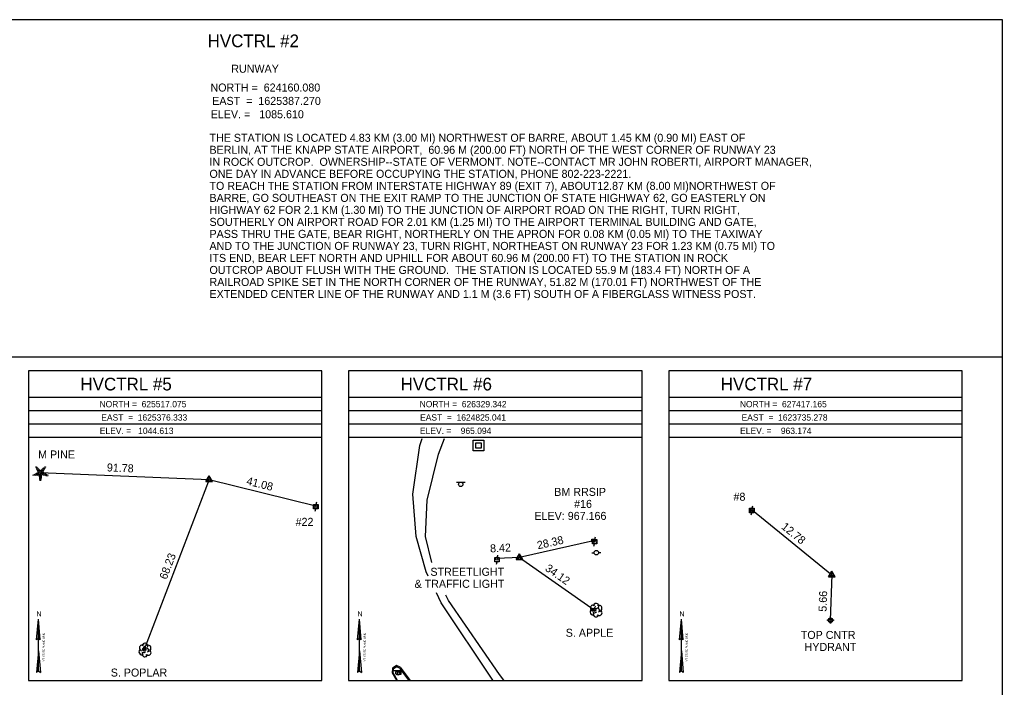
# Model space of a CAD drawing. Extents: x 1624370 to 1625010, y 624015 to 624435.
# Drawn here: x 1624641.5 to 1625009.8, y 624185.4 to 624435.5 of the extents above; entities that cross this region are included whole.
import ezdxf

# ---------------------------------------------------------------- set-up
doc = ezdxf.new("R2010")
doc.units = 0
for name, color, linetype in [('C_C', 7, 'Continuous'), ('CBP', 7, 'Continuous'), ('CPBM', 7, 'Continuous'), ('CPSM', 7, 'Continuous'), ('Default', 7, 'Continuous'), ('DS', 7, 'Continuous'), ('L_C', 7, 'Continuous'), ('LTC', 7, 'Continuous'), ('LTD', 7, 'Continuous'), ('NBL1', 7, 'Continuous'), ('NBL2', 7, 'Continuous'), ('NNA_P', 7, 'Continuous'), ('PET', 7, 'Continuous'), ('PSP', 7, 'Continuous'), ('RC', 7, 'Continuous'), ('SRM', 7, 'Continuous'), ('SSGN', 7, 'Continuous'), ('U_C', 7, 'Continuous'), ('ULP', 7, 'Continuous'), ('UP', 7, 'Continuous'), ('UWFH', 7, 'Continuous')]:
    doc.layers.add(name, color=color, linetype=linetype)

msp = doc.modelspace()

# ---------------------------------------------------------------- linework, layer by layer
at = {"layer": 'CBP'}
for centre, radius in [((1624649.13, 624265.8), 0.625), ((1624649.13, 624265.8), 0.0833), ((1624752.44, 624253.33), 0.625), ((1624752.44, 624253.33), 0.0833), ((1624916.17, 624251.76), 0.625), ((1624916.17, 624251.76), 0.0833), ((1624856.56, 624240.21), 0.625), ((1624856.56, 624240.21), 0.0833), ((1624820.45, 624233.6), 0.625), ((1624820.45, 624233.6), 0.0833), ((1624856.84, 624214.46), 0.625), ((1624856.84, 624214.46), 0.0833), ((1624945.27, 624210.52), 0.625), ((1624945.27, 624210.52), 0.0833), ((1624688.15, 624199.5), 0.625), ((1624688.15, 624199.5), 0.0833)]:
    msp.add_circle(centre, radius, dxfattribs=at)
at = {"layer": 'CPBM'}
for p, q in [((1624855.95, 624239.93), (1624855.95, 624240.93)), ((1624855.95, 624240.93), (1624856.95, 624240.93)), ((1624856.95, 624239.93), (1624855.95, 624239.93)), ((1624856.45, 624240.43), (1624856.45, 624240.43)), ((1624856.45, 624240.43), (1624856.45, 624240.43)), ((1624856.95, 624240.93), (1624856.95, 624239.93))]:
    msp.add_line(p, q, dxfattribs=at)
at = {"layer": 'CPSM'}
for p, q in [((1624711.31, 624262.5), (1624712.56, 624264.67)), ((1624711.31, 624262.5), (1624712.56, 624263.22)), ((1624711.31, 624262.5), (1624713.81, 624262.5)), ((1624713.81, 624262.5), (1624712.56, 624264.67)), ((1624712.56, 624263.22), (1624712.56, 624264.67)), ((1624712.56, 624263.22), (1624712.56, 624263.22)), ((1624712.56, 624263.22), (1624713.81, 624262.5)), ((1624827.61, 624233.28), (1624828.86, 624235.45)), ((1624827.61, 624233.28), (1624828.86, 624234)), ((1624827.61, 624233.28), (1624830.11, 624233.28)), ((1624830.11, 624233.28), (1624828.86, 624235.45)), ((1624828.86, 624234), (1624828.86, 624235.45)), ((1624828.86, 624234), (1624828.86, 624234)), ((1624828.86, 624234), (1624830.11, 624233.28)), ((1624944.61, 624226.78), (1624945.86, 624228.95)), ((1624947.11, 624226.78), (1624945.86, 624228.95)), ((1624945.86, 624227.51), (1624945.86, 624228.95)), ((1624944.61, 624226.78), (1624945.86, 624227.51)), ((1624944.61, 624226.78), (1624947.11, 624226.78)), ((1624945.86, 624227.51), (1624945.86, 624227.51)), ((1624945.86, 624227.51), (1624947.11, 624226.78))]:
    msp.add_line(p, q, dxfattribs=at)
at = {"layer": 'Default'}
for p, q in [((1624649.13, 624265.8), (1624712.56, 624263.22)), ((1624712.56, 624263.22), (1624688.15, 624199.5)), ((1624712.56, 624263.22), (1624752.44, 624253.33)), ((1624916.17, 624251.76), (1624945.87, 624227.5)), ((1624856.56, 624240.21), (1624828.86, 624234)), ((1624828.86, 624234), (1624820.45, 624233.6)), ((1624828.86, 624234), (1624856.84, 624214.46)), ((1624945.87, 624227.5), (1624945.27, 624210.52))]:
    msp.add_line(p, q, dxfattribs=at)
at = {"layer": 'DS'}
for p, q in [((1624811.47, 624277.96), (1624815.47, 624277.96)), ((1624811.47, 624273.96), (1624811.47, 624277.96)), ((1624812.47, 624274.96), (1624812.47, 624276.96)), ((1624812.47, 624276.96), (1624814.47, 624276.96)), ((1624814.47, 624276.96), (1624814.47, 624274.96)), ((1624815.47, 624277.96), (1624815.47, 624273.96)), ((1624815.47, 624273.96), (1624811.47, 624273.96)), ((1624814.47, 624274.96), (1624812.47, 624274.96)), ((1624813.48, 624275.96), (1624813.48, 624275.96)), ((1624813.48, 624275.96), (1624813.48, 624275.96))]:
    msp.add_line(p, q, dxfattribs=at)
at = {"layer": 'LTC'}
for p, q in [((1624646.9, 624265.37), (1624647.11, 624264.72)), ((1624647.36, 624265.59), (1624647.63, 624264.75)), ((1624647.42, 624267.88), (1624647.77, 624268.14)), ((1624647.62, 624267.41), (1624648.15, 624267.8)), ((1624647.81, 624265.81), (1624648.14, 624264.79)), ((1624647.83, 624266.95), (1624648.54, 624267.46)), ((1624648.04, 624266.48), (1624648.92, 624267.12)), ((1624648.27, 624266.03), (1624649.28, 624266.76)), ((1624648.27, 624266.03), (1624648.66, 624264.83)), ((1624649.28, 624266.76), (1624650.28, 624266.04)), ((1624649.7, 624267.07), (1624650.51, 624266.48)), ((1624650.28, 624266.04), (1624649.89, 624264.83)), ((1624650.07, 624267.42), (1624650.75, 624266.93)), ((1624650.71, 624265.76), (1624650.38, 624264.72)), ((1624650.44, 624267.77), (1624650.99, 624267.37)), ((1624650.81, 624268.12), (1624651.23, 624267.81)), ((1624651.16, 624265.51), (1624650.87, 624264.63)), ((1624651.6, 624265.26), (1624651.37, 624264.53)), ((1624646.45, 624265.16), (1624646.6, 624264.69)), ((1624649.89, 624264.83), (1624648.66, 624264.83)), ((1624649.85, 624264.33), (1624648.7, 624264.33)), ((1624649.76, 624263.83), (1624648.78, 624263.83)), ((1624649.68, 624263.33), (1624648.85, 624263.33)), ((1624649.6, 624262.83), (1624648.92, 624262.83)), ((1624652.05, 624265.01), (1624651.86, 624264.44))]:
    msp.add_line(p, q, dxfattribs=at)
at = {"layer": 'LTD'}
for p, q in [((1624857.47, 624214.33), (1624857.47, 624214.33)), ((1624857.47, 624214.33), (1624857.47, 624214.33)), ((1624688.44, 624199.42), (1624688.44, 624199.42)), ((1624688.44, 624199.42), (1624688.44, 624199.42))]:
    msp.add_line(p, q, dxfattribs=at)
for centre in [(1624857.52, 624215.76), (1624688.48, 624200.86)]:
    msp.add_arc(centre, 1.05, 335.5272, 180.9563, dxfattribs=at)
for centre, major_axis, ratio, start_param, end_param in [((1624856.39, 624213.62), (0.58, -1.04), 0.959034, 3.141593, 6.283185), ((1624856.68, 624215), (1.21, -0.51), 0.895232, 1.570796, 4.712389), ((1624857.01, 624213.58), (-0.625, -0.083), 0.423636, 0, 3.141593), ((1624857.26, 624214.79), (-0.208, -0.792), 0.645439, 3.141593, 6.283185), ((1624857.97, 624214.16), (-0.5, 0.667), 0.989748, 3.141593, 6.283185), ((1624858.47, 624213.5), (-1.09, 0.79), 0.841452, 1.570796, 4.712389), ((1624858.51, 624214.91), (-1.14, -0.48), 0.949671, 1.570796, 4.712389), ((1624857.47, 624212.83), (0.26, 1.06), 0.942809, 1.570796, 4.712389), ((1624687.35, 624198.72), (0.58, -1.04), 0.959034, 3.141593, 6.283185), ((1624687.65, 624200.09), (1.21, -0.51), 0.895232, 1.570796, 4.712389), ((1624688.23, 624199.88), (-0.208, -0.792), 0.645439, 3.141593, 6.283185), ((1624688.94, 624199.26), (-0.5, 0.667), 0.989748, 3.141593, 6.283185), ((1624689.44, 624198.59), (-1.09, 0.79), 0.841452, 1.570796, 4.712389), ((1624689.48, 624200.01), (-1.14, -0.48), 0.949671, 1.570796, 4.712389), ((1624688.44, 624197.92), (0.26, 1.06), 0.942809, 1.570796, 4.712389), ((1624687.98, 624198.67), (-0.625, -0.083), 0.423636, 0, 3.141593)]:
    msp.add_ellipse(centre, major_axis=major_axis, ratio=ratio, start_param=start_param, end_param=end_param, dxfattribs=at)
at = {"layer": 'NBL1'}
msp.add_lwpolyline([(1624369.79, 624015.47), (1625009.79, 624015.47), (1625009.79, 624435.47), (1624369.79, 624435.47)], close=True, dxfattribs=at)
at = {"layer": 'NBL2'}
for p, q in [((1624369.79, 624309.14), (1625009.79, 624309.14)), ((1624754.79, 624293.97), (1624644.79, 624293.97)), ((1624874.79, 624293.97), (1624764.79, 624293.97)), ((1624994.79, 624293.97), (1624884.79, 624293.97)), ((1624754.79, 624288.97), (1624644.79, 624288.97)), ((1624874.79, 624288.97), (1624764.79, 624288.97)), ((1624994.79, 624288.97), (1624884.79, 624288.97)), ((1624754.79, 624283.97), (1624644.79, 624283.97)), ((1624874.79, 624283.97), (1624764.79, 624283.97)), ((1624994.79, 624283.97), (1624884.79, 624283.97)), ((1624754.79, 624278.97), (1624644.79, 624278.97)), ((1624874.79, 624278.97), (1624764.79, 624278.97)), ((1624994.79, 624278.97), (1624884.79, 624278.97))]:
    msp.add_line(p, q, dxfattribs=at)
for points in [[(1624644.79, 624187.97), (1624754.79, 624187.97), (1624754.79, 624303.97), (1624644.79, 624303.97)], [(1624764.79, 624187.97), (1624874.79, 624187.97), (1624874.79, 624303.97), (1624764.79, 624303.97)], [(1624884.79, 624187.97), (1624994.79, 624187.97), (1624994.79, 624303.97), (1624884.79, 624303.97)]]:
    msp.add_lwpolyline(points, close=True, dxfattribs=at)
at = {"layer": 'NNA_P'}
for p, q in [((1624647.81, 624203.13), (1624648.51, 624210.92)), ((1624648.51, 624191.55), (1624648.51, 624210.92)), ((1624649.2, 624203.13), (1624648.51, 624210.92)), ((1624768.13, 624203.13), (1624768.82, 624210.92)), ((1624768.82, 624191.55), (1624768.82, 624210.92)), ((1624769.51, 624203.13), (1624768.82, 624210.92)), ((1624888.79, 624203.13), (1624889.49, 624210.92)), ((1624889.49, 624191.55), (1624889.49, 624210.92)), ((1624890.18, 624203.13), (1624889.49, 624210.92)), ((1624647.81, 624203.13), (1624648.51, 624203.9)), ((1624649.2, 624203.13), (1624648.51, 624203.9)), ((1624768.13, 624203.13), (1624768.82, 624203.9)), ((1624769.52, 624203.13), (1624768.82, 624203.9)), ((1624888.79, 624203.13), (1624889.49, 624203.9)), ((1624890.18, 624203.13), (1624889.49, 624203.9)), ((1624648.51, 624199.08), (1624647.79, 624190.91)), ((1624648.51, 624199.08), (1624649.23, 624190.91)), ((1624768.83, 624199.08), (1624768.1, 624190.91)), ((1624768.82, 624199.08), (1624769.54, 624190.91)), ((1624889.49, 624199.08), (1624888.77, 624190.91)), ((1624889.49, 624199.08), (1624890.21, 624190.91)), ((1624648.51, 624191.55), (1624647.79, 624190.91)), ((1624648.51, 624191.55), (1624649.23, 624190.91)), ((1624768.82, 624191.55), (1624768.1, 624190.91)), ((1624768.82, 624191.55), (1624769.54, 624190.91)), ((1624889.49, 624191.55), (1624888.77, 624190.91)), ((1624889.49, 624191.55), (1624890.21, 624190.91))]:
    msp.add_line(p, q, dxfattribs=at)
at = {"layer": 'PET'}
for points in [[(1624794.6, 624227.06), (1624793.79, 624228.69), (1624790.08, 624241.83), (1624788.9, 624257.7), (1624791.48, 624275.91), (1624792.31, 624278.64)], [(1624818.82, 624188.1), (1624799.51, 624217.07), (1624797.7, 624220.75)], [(1624784.11, 624192.9), (1624782.66, 624193.51), (1624781.17, 624192.55), (1624781.09, 624190.84), (1624782.75, 624188.1)], [(1624784.11, 624192.9), (1624787.69, 624188.1)]]:
    msp.add_lwpolyline(points, dxfattribs=at)
at = {"layer": 'PSP'}
for points in [[(1624795.92, 624232.14), (1624793.57, 624241.85), (1624794.24, 624255.51), (1624798.47, 624272.7), (1624800.77, 624278.64)], [(1624822.92, 624188.1), (1624821.37, 624190.19), (1624802.26, 624217.89), (1624801.27, 624219.9)]]:
    msp.add_lwpolyline(points, dxfattribs=at)
at = {"layer": 'RC'}
for points in [[(1624783.81, 624192.6), (1624782.73, 624193.08), (1624781.46, 624192.2), (1624781.3, 624190.97), (1624783.03, 624188.1)], [(1624783.81, 624192.6), (1624787.18, 624188.1)]]:
    msp.add_lwpolyline(points, dxfattribs=at)
at = {"layer": 'SRM'}
msp.add_lwpolyline([(1624783.08, 624191.5), (1624784.33, 624191.5), (1624784.33, 624190.25), (1624783.08, 624190.25)], close=True, dxfattribs=at)
msp.add_circle((1624783.7, 624190.88), 0.0833, dxfattribs=at)
at = {"layer": 'SSGN'}
for p, q in [((1624805.15, 624262.26), (1624808.49, 624262.26)), ((1624806.8, 624261.43), (1624806.8, 624261.43)), ((1624781.6, 624191.66), (1624784.93, 624191.66)), ((1624783.25, 624190.83), (1624783.25, 624190.83))]:
    msp.add_line(p, q, dxfattribs=at)
for centre in [(1624806.8, 624261.43), (1624783.25, 624190.83)]:
    msp.add_circle(centre, 0.833, dxfattribs=at)
at = {"layer": 'ULP'}
for p, q in [((1624819.56, 624232.35), (1624819.56, 624234.02)), ((1624819.56, 624234.02), (1624821.23, 624234.02)), ((1624821.23, 624232.35), (1624819.56, 624232.35)), ((1624820.14, 624231.52), (1624820.39, 624232.35)), ((1624820.56, 624234.85), (1624820.39, 624234.02)), ((1624820.39, 624233.19), (1624820.39, 624233.19)), ((1624821.23, 624234.02), (1624821.23, 624232.35))]:
    msp.add_line(p, q, dxfattribs=at)
at = {"layer": 'UP'}
for p, q in [((1624752.74, 624254.69), (1624752.49, 624253.86)), ((1624751.65, 624252.19), (1624751.65, 624253.86)), ((1624751.65, 624253.86), (1624753.32, 624253.86)), ((1624753.32, 624252.19), (1624751.65, 624252.19)), ((1624752.24, 624251.36), (1624752.49, 624252.19)), ((1624752.49, 624253.03), (1624752.49, 624253.03)), ((1624753.32, 624253.86), (1624753.32, 624252.19)), ((1624915.07, 624250.8), (1624915.07, 624252.47)), ((1624915.07, 624252.47), (1624916.74, 624252.47)), ((1624916.74, 624250.8), (1624915.07, 624250.8)), ((1624915.66, 624249.97), (1624915.91, 624250.8)), ((1624916.16, 624253.3), (1624915.91, 624252.47)), ((1624915.91, 624251.64), (1624915.91, 624251.64)), ((1624916.74, 624252.47), (1624916.74, 624250.8)), ((1624856.12, 624239.08), (1624856.12, 624240.75)), ((1624856.12, 624240.75), (1624857.79, 624240.75)), ((1624857.21, 624241.58), (1624856.96, 624240.75)), ((1624856.96, 624239.92), (1624856.96, 624239.92)), ((1624857.79, 624240.75), (1624857.79, 624239.08)), ((1624855.94, 624235.82), (1624856.77, 624235.82)), ((1624857.79, 624239.08), (1624856.12, 624239.08)), ((1624856.71, 624238.25), (1624856.96, 624239.08)), ((1624857.6, 624235.83), (1624857.6, 624235.83)), ((1624859.27, 624235.83), (1624858.44, 624235.83)), ((1624858.44, 624235.83), (1624858.44, 624235.83)), ((1624859.27, 624235.83), (1624859.27, 624235.83))]:
    msp.add_line(p, q, dxfattribs=at)
for centre in [(1624752.49, 624253.03), (1624915.91, 624251.64), (1624856.96, 624239.92), (1624857.6, 624235.83)]:
    msp.add_circle(centre, 0.833, dxfattribs=at)
at = {"layer": 'UWFH'}
msp.add_line((1624945.37, 624210.55), (1624945.37, 624210.55), dxfattribs=at)
for centre, radius in [((1624944.37, 624210.55), 0.167), ((1624945.37, 624210.55), 0.833), ((1624946.37, 624210.55), 0.167), ((1624945.37, 624209.55), 0.167)]:
    msp.add_circle(centre, radius, dxfattribs=at)

# ---------------------------------------------------------------- texts
at = {"layer": 'C_C'}
for s, p in [('TOP CNTR', (1624934.24, 624203.52)), ('HYDRANT', (1624935.67, 624199.02))]:
    msp.add_text(s, height=3, dxfattribs=at).set_placement(p)
at = {"layer": 'Default'}
for s, p in [('THE STATION IS LOCATED 4.83 KM (3.00 MI) NORTHWEST OF BARRE, ABOUT 1.45 KM (0.90 MI) EAST OF ', (1624712.62, 624389.73)), ('BERLIN, AT THE KNAPP STATE AIRPORT,  60.96 M (200.00 FT) NORTH OF THE WEST CORNER OF RUNWAY 23 ', (1624712.62, 624385.23)), ('IN ROCK OUTCROP.  OWNERSHIP--STATE OF VERMONT. NOTE--CONTACT MR JOHN ROBERTI, AIRPORT MANAGER, ', (1624712.62, 624380.73)), ('ONE DAY IN ADVANCE BEFORE OCCUPYING THE STATION, PHONE 802-223-2221.  ', (1624712.62, 624376.23)), ('TO REACH THE STATION FROM INTERSTATE HIGHWAY 89 (EXIT 7), ABOUT12.87 KM (8.00 MI)NORTHWEST OF ', (1624712.62, 624371.73)), ('BARRE, GO SOUTHEAST ON THE EXIT RAMP TO THE JUNCTION OF STATE HIGHWAY 62, GO EASTERLY ON ', (1624712.62, 624367.23)), ('HIGHWAY 62 FOR 2.1 KM (1.30 MI) TO THE JUNCTION OF AIRPORT ROAD ON THE RIGHT, TURN RIGHT, ', (1624712.62, 624362.73)), ('SOUTHERLY ON AIRPORT ROAD FOR 2.01 KM (1.25 MI) TO THE AIRPORT TERMINAL BUILDING AND GATE, ', (1624712.62, 624358.23)), ('PASS THRU THE GATE, BEAR RIGHT, NORTHERLY ON THE APRON FOR 0.08 KM (0.05 MI) TO THE TAXIWAY ', (1624712.62, 624353.73)), ('AND TO THE JUNCTION OF RUNWAY 23, TURN RIGHT, NORTHEAST ON RUNWAY 23 FOR 1.23 KM (0.75 MI) TO ', (1624712.62, 624349.23)), ('ITS END, BEAR LEFT NORTH AND UPHILL FOR ABOUT 60.96 M (200.00 FT) TO THE STATION IN ROCK ', (1624712.62, 624344.73)), ('OUTCROP ABOUT FLUSH WITH THE GROUND.  THE STATION IS LOCATED 55.9 M (183.4 FT) NORTH OF A ', (1624712.62, 624340.23)), ('RAILROAD SPIKE SET IN THE NORTH CORNER OF THE RUNWAY, 51.82 M (170.01 FT) NORTHWEST OF THE ', (1624712.62, 624335.73)), ('EXTENDED CENTER LINE OF THE RUNWAY AND 1.1 M (3.6 FT) SOUTH OF A FIBERGLASS WITNESS POST.', (1624712.62, 624331.23))]:
    msp.add_text(s, height=3, dxfattribs=at).set_placement(p)
for s, rotation, p in [('91.78', 357.6781, (1624674.12, 624266.28)), ('41.08', 346.0665, (1624726.27, 624261.37)), ('12.78', 320.7592, (1624926.71, 624245.09)), ('28.38', 12.6252, (1624835.76, 624237.08)), ('8.42', 2.7251, (1624817.86, 624235.91)), ('68.23', 69.0381, (1624696.53, 624225.56)), ('34.12', 325.0568, (1624838.14, 624229.35)), ('5.66', 87.9759, (1624943.88, 624213.68))]:
    msp.add_text(s, height=3, rotation=rotation, dxfattribs=at).set_placement(p)
at = {"layer": 'L_C'}
for s, p in [('M PINE', (1624648.39, 624271.12)), ('S. APPLE', (1624846.15, 624204.33)), ('S. POPLAR', (1624675.61, 624189.42))]:
    msp.add_text(s, height=3, dxfattribs=at).set_placement(p)
at = {"layer": 'LTC'}
msp.add_text('.', height=1.04, rotation=270, dxfattribs=at).set_placement((1624649.16, 624265.77))
at = {"layer": 'NBL2'}
for s, height, p in [('     HVCTRL #2     ', 4.75, (1624703.11, 624425.17)), ('       RUNWAY       ', 3, (1624712.99, 624415.6)), ('NORTH =  624160.080 ', 3, (1624712.99, 624408.55)), ('EAST  =  1625387.270', 3, (1624713.65, 624403.55)), ('ELEV. =   1085.610  ', 3, (1624713.09, 624398.55)), ('     HVCTRL #5     ', 4.75, (1624655.43, 624296.6)), ('     HVCTRL #6     ', 4.75, (1624775.43, 624296.6)), ('     HVCTRL #7     ', 4.75, (1624895.43, 624296.6)), ('NORTH =  625517.075 ', 2.375, (1624671.4, 624290.29)), ('NORTH =  626329.342 ', 2.375, (1624791.4, 624290.29)), ('NORTH =  627417.165 ', 2.375, (1624911.4, 624290.29)), ('EAST  =  1625376.333', 2.375, (1624672.06, 624285.29)), ('EAST  =  1624825.041', 2.375, (1624791.55, 624285.29)), ('EAST  =  1623735.278', 2.375, (1624912.06, 624285.29)), ('ELEV. =   1044.613  ', 2.375, (1624671.51, 624280.29)), ('ELEV. =    965.094  ', 2.375, (1624791.51, 624280.29)), ('ELEV. =    963.174  ', 2.375, (1624911.51, 624280.29))]:
    msp.add_text(s, height=height, dxfattribs=at).set_placement(p)
at = {"layer": 'NNA_P'}
for p in [(1624647.74, 624211.94), (1624768.06, 624211.94), (1624888.73, 624211.94)]:
    msp.add_text('N', height=1.97, dxfattribs=at).set_placement(p)
for p in [(1624650.86, 624195.11), (1624771.17, 624195.11), (1624891.84, 624195.11)]:
    msp.add_text('VT STATE PLANE GRID', height=0.7, rotation=90.0204, dxfattribs=at).set_placement(p)
at = {"layer": 'U_C'}
for s, p in [('BM RRSIP', (1624841.85, 624257.1)), ('#8', (1624909.03, 624255.28)), ('#16', (1624849.29, 624252.6)), ('ELEV: 967.166', (1624834.41, 624248.1)), ('#22', (1624744.9, 624245.88)), ('STREETLIGHT', (1624795.43, 624227.17)), ('& TRAFFIC LIGHT', (1624789.48, 624222.67))]:
    msp.add_text(s, height=3, dxfattribs=at).set_placement(p)

doc.saveas('drawing.dxf')
